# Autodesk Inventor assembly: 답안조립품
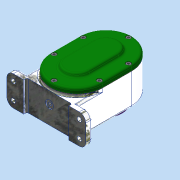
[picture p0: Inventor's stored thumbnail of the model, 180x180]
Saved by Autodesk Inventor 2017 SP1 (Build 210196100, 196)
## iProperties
Part Number: 답안조립품
Material: 일반
Document SubType Name: Assembly
Designer: MRC
Author: MRC
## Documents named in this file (19)
- C:\Users\MRC\Desktop\710609V1001\답안조립품.iam
- C:\Users\MRC\Desktop\710609V1001\본체.ipt
- C:\Users\MRC\Desktop\710609V1001\개스킷 A.ipt
- C:\Users\MRC\Desktop\710609V1001\개스킷 B.ipt
- C:\Users\MRC\Desktop\710609V1001\베어링 6001.ipt
- 베어링 6001.ipt
- C:\Users\MRC\Desktop\710609V1001\베어링 6002.ipt
- 베어링 6002.ipt
- C:\Users\MRC\Desktop\710609V1001\볼트 M4.ipt
- C:\Users\MRC\Desktop\710609V1001\스퍼기어 A.ipt
- C:\Users\MRC\Desktop\710609V1001\스퍼기어 B.ipt
- C:\Users\MRC\Desktop\710609V1001\오일 실 12 22 7.ipt
- C:\Users\MRC\Desktop\710609V1001\축 A.ipt
- C:\Users\MRC\Desktop\710609V1001\축 B.ipt
- C:\Users\MRC\Desktop\710609V1001\칼라.ipt
- C:\Users\MRC\Desktop\710609V1001\커버 A.ipt
- C:\Users\MRC\Desktop\710609V1001\커버 B.ipt
- C:\Users\MRC\Desktop\710609V1001\키 4 x 4 x 12.ipt
- C:\Users\MRC\Desktop\710609V1001\키 5 x 5 x 12.ipt
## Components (2 placed, 2 different names)
1. 개스킷 A:1
2. 개스킷 B:1
